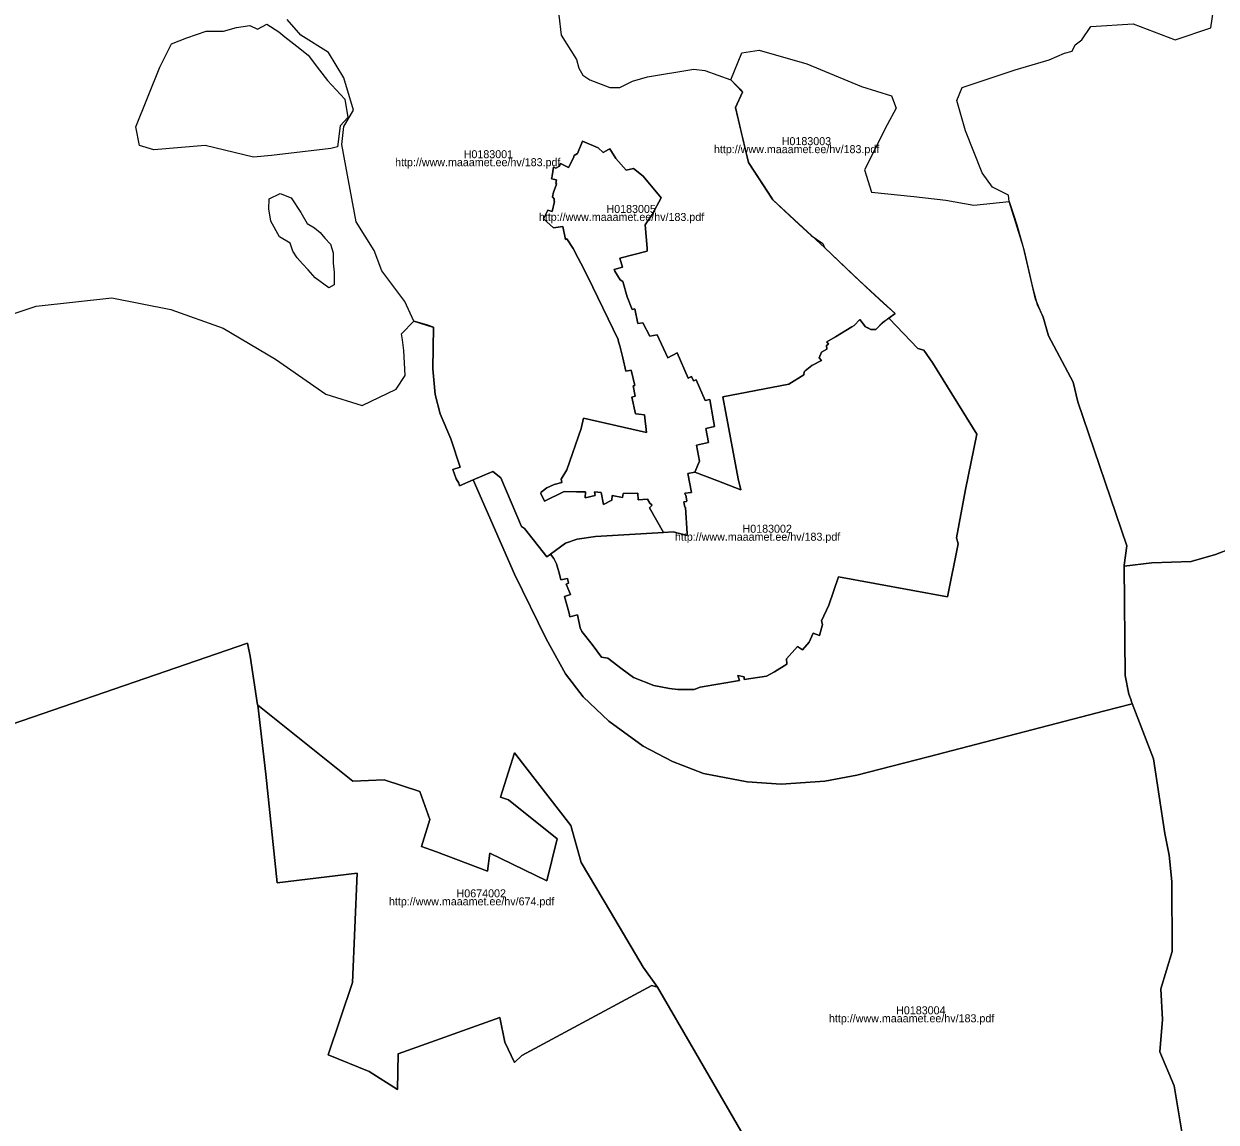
# Model space of a CAD drawing. Extents: x 369010 to 739155, y 6377141 to 6634081.
# Drawn here: x 471593 to 475318, y 6531445 to 6534877 of the extents above; entities that cross this region are included whole.
import ezdxf

# ---------------------------------------------------------------- set-up
doc = ezdxf.new("R2010")
doc.units = 0
for name, color, linetype in [('H_LINK', 7, 'Continuous'), ('H_PIIR', 7, 'Continuous'), ('H_TUNNUS', 7, 'Continuous')]:
    doc.layers.add(name, color=color, linetype=linetype)

msp = doc.modelspace()

# ---------------------------------------------------------------- linework, layer by layer
at = {"layer": 'H_PIIR'}
for points in [[(475364.8401, 6533237.45), (475316.2799, 6533219.06), (475239.38, 6533197), (475117.2199, 6533193.4201), (475030.3393, 6533182.4787), (475030.3, 6533186.16), (475039.08, 6533246.02), (474885.8701, 6533696.14), (474870.9001, 6533757.78), (474794.1099, 6533901.8299), (474777.21, 6533960.43), (474753.57, 6534017.02), (474715.6, 6534178.31), (474671.2069, 6534322.0591), (474668.6933, 6534341.3737), (474619.0839, 6534366.5091), (474587.3338, 6534411.4884), (474534.313, 6534542.6387), (474507.3254, 6534637.8889), (474524.788, 6534677.5765), (474689.8883, 6534733.1391), (474796.251, 6534764.8892), (474843.8761, 6534785.5267), (474867.6886, 6534791.8767), (474877.2137, 6534810.9267), (474898.1158, 6534826.8018), (474925.8971, 6534869.1352), (475058.189, 6534877.0727), (475189.9518, 6534826.8018), (475300.8124, 6534864.3727), (475319.3333, 6534984.7583)], [(473264.6791, 6534903.9142), (473271.84, 6534841.7599), (473319.9099, 6534765.46), (473326.52, 6534738.5501), (473339.75, 6534716.0601), (473361.3599, 6534701.4999), (473423.61, 6534678.29), (473454.49, 6534678.29), (473494.1801, 6534698.1301), (473541.3699, 6534711.81), (473686.46, 6534735.6301), (473719.98, 6534731.6601), (473801.71, 6534701.78), (473831.2103, 6534672.9801), (473838.55, 6534663.64), (473815.9, 6534615.14), (473835.0722, 6534534.3921), (473856.5102, 6534444.1018), (473918.52, 6534350.37), (473932.8083, 6534327.2742), (473969.4036, 6534293.0652), (474015.2445, 6534250.2137), (474052.5765, 6534215.3161), (474088.572, 6534191.1336), (474093.8573, 6534178.106), (474222.6456, 6534056.3373), (474280.0158, 6534002.7083), (474314.98, 6533971.86), (474294.8903, 6533957.742), (474271.0477, 6533938.6733), (474255, 6533922.0099), (474238.68, 6533922.46), (474229.6719, 6533926.8398), (474222.3701, 6533930.39), (474204.6842, 6533953.5152), (474187.2001, 6533934.2001), (474179.9671, 6533929.9246), (474128.41, 6533899.4499), (474101.2601, 6533883.81), (474106.8199, 6533876.4299), (474100.17, 6533871.8801), (474101.0799, 6533860.9601), (474084.61, 6533851.5599), (474077.93, 6533833.6799), (474084.61, 6533825.33), (474054.3599, 6533809.0501), (474033.38, 6533792.7399), (474030.36, 6533789.49), (474030.01, 6533780.7201), (473982.64, 6533750.6399), (473776.47, 6533712.0401), (473825.06, 6533455.58), (473832.47, 6533420.97), (473758.02, 6533450.6701), (473689.2901, 6533475.82), (473704.2301, 6533510.8), (473693.94, 6533560.2699), (473732.13, 6533568.4801), (473723.97, 6533612.35), (473750.8299, 6533618.81), (473747.82, 6533636.9299), (473735.9299, 6533703.25), (473721.87, 6533700.4399), (473693.1599, 6533764.6601), (473685.03, 6533761.1401), (473678.2601, 6533774.69), (473668.28, 6533770.2599), (473634.4201, 6533848.57), (473604.3699, 6533833.6), (473571.3799, 6533905.2899), (473548.8999, 6533901.5), (473527.23, 6533943.23), (473511.04, 6533940.18), (473501.99, 6533986.0699), (473493.16, 6533984.62), (473478.28, 6534024.0999), (473464.32, 6534071.77), (473455.5601, 6534076.6599), (473439.3701, 6534104.09), (473437.5499, 6534109.72), (473463.1301, 6534117.1601), (473455.16, 6534144.98), (473540.66, 6534166.83), (473540.1, 6534175.9901), (473533.78, 6534248.94), (473555.67, 6534281.27), (473584.2201, 6534333.7), (473528.2901, 6534400.54), (473497.5699, 6534425.36), (473474.7, 6534419.9099), (473442.07, 6534455.8401), (473423.2601, 6534486.2799), (473419.33, 6534484.42), (473402.78, 6534474.68), (473386.9001, 6534489.8401), (473338.53, 6534510.77), (473322.99, 6534471.8399), (473312.16, 6534465.23), (473309.9, 6534458.23), (473294.31, 6534428.35), (473275.84, 6534437.2399), (473276.0399, 6534437.7899), (473269.59, 6534440.1299), (473266.09, 6534431.79), (473255, 6534426.14), (473247.45, 6534428.92), (473243, 6534401.5401), (473243.6899, 6534401.4), (473241.85, 6534392.2099), (473257.0099, 6534389.2), (473254.54, 6534378.31), (473256.77, 6534378.03), (473256.12, 6534373.02), (473247.6, 6534350.5), (473244.3099, 6534336.69), (473249.41, 6534329.85), (473249.41, 6534322.2), (473251.13, 6534321.8099), (473243, 6534291.1), (473229.9501, 6534294.2701), (473216.77, 6534267.5999), (473247.8701, 6534239.75), (473276.7501, 6534243.77), (473285.4301, 6534203.1501), (473289.3701, 6534205.2599), (473308.71, 6534174.8701), (473324.81, 6534144.44), (473341.8801, 6534114.07), (473370.48, 6534053.89), (473449.55, 6533891.1), (473450.8299, 6533882.98), (473454.71, 6533870.8201), (473463.92, 6533833.1399), (473473.56, 6533791.5799), (473489.79, 6533795), (473502.09, 6533747.1399), (473496.5501, 6533745.83), (473503.08, 6533713.2001), (473492.4399, 6533710.72), (473503.72, 6533658.4401), (473513.94, 6533657.37), (473532.1, 6533654.8299), (473538.19, 6533600.42), (473341.3301, 6533645.0899), (473333.9, 6533612.8501), (473288.8101, 6533483.5601), (473271.19, 6533454.54), (473273.7199, 6533444.2999), (473249.38, 6533437.59), (473226.4199, 6533427.0901), (473209.2001, 6533413.6499), (473207.8799, 6533410.05), (473219.39, 6533385.3799), (473281.03, 6533416.1301), (473319.74, 6533415.27), (473347.85, 6533414.8299), (473346.5801, 6533396.4601), (473378.1399, 6533403.79), (473376.08, 6533414.73), (473396.48, 6533412.6901), (473403.75, 6533374.68), (473430.36, 6533389.0501), (473431.3901, 6533403.2799), (473463.5699, 6533396.74), (473465.2799, 6533409.2201), (473510.8299, 6533410.9201), (473511.9599, 6533390.0299), (473541.26, 6533391.3401), (473548.54, 6533378.89), (473555.3199, 6533374.5701), (473554.0899, 6533370.87), (473547.3001, 6533364.7001), (473590.94, 6533287.7), (473379.09, 6533275.39), (473321.6901, 6533266.7201), (473285.3101, 6533254.8), (473238.21, 6533220.03), (473226.4199, 6533211.44), (473157.38, 6533300.1901), (473147.17, 6533306.4401), (473082.8901, 6533458.91), (473058.33, 6533478.3901), (472996.63, 6533452.4501), (472954.35, 6533433.9801), (472951.7199, 6533441.4401), (472943.3, 6533455.2199), (472933.3299, 6533484.92), (472955.56, 6533492.2801), (472926.68, 6533580.31), (472893.93, 6533658.3299), (472877.55, 6533718.82), (472870.17, 6533799.52), (472872.819, 6533929.3015), (472851.7959, 6533936.8073), (472811.4469, 6533948.0521), (472783.6656, 6534009.5679), (472711.5665, 6534104.8181), (472687.754, 6534168.3182), (472631.5299, 6534258.2767), (472598.3246, 6534432.4258), (472586.4183, 6534499.8947), (472592.3715, 6534556.1188), (472622.7986, 6534607.0511), (472592.3715, 6534708.2545), (472544.7464, 6534786.9682), (472458.7566, 6534841.2079), (472415.1576, 6534890.5327)], [(471456.7687, 6533936.3928), (471631.3941, 6533994.6012), (471868.1966, 6534021.0596), (472052.0824, 6533984.0179), (472216.1244, 6533925.8094), (472378.8435, 6533829.2363), (472536.2709, 6533719.434), (472650.0419, 6533684.2885), (472755.8755, 6533735.0886), (472784.4505, 6533777.9512), (472779.9614, 6533856.1092), (472775.7281, 6533889.4468), (472773.0822, 6533908.3645), (472811.4469, 6533948.0521), (472870.83, 6533929.4), (472872.819, 6533929.3015), (472870.17, 6533799.52), (472877.55, 6533718.82), (472893.93, 6533658.3299), (472926.68, 6533580.31), (472955.56, 6533492.2801), (472933.3299, 6533484.92), (472943.3, 6533455.2199), (472951.7199, 6533441.4401), (472954.35, 6533433.9801), (472996.63, 6533452.4501), (473125.5301, 6533157.43), (473225.17, 6532955.5399), (473284.7299, 6532845.77), (473340.1701, 6532774.3), (473420.4101, 6532698.7599), (473527.33, 6532620.58), (473619.01, 6532571.72), (473716.56, 6532535.0001), (473852.22, 6532508.9399), (473958.4, 6532500.9199), (474095.4601, 6532510.95), (474195.1699, 6532529.03), (474418.35, 6532586.53), (474969.68, 6532730.25), (475051.0512, 6532751.8103), (475055.993, 6532753.1197), (475122.11, 6532580.6201), (475157.79, 6532346.77), (475170.7, 6532279.62), (475179.92, 6532197.13), (475180.1401, 6531978.1199), (475145.27, 6531862.49), (475150.0199, 6531765.75), (475141.82, 6531664.68), (475187.2, 6531559.17), (475224.34, 6531333.9)], [(475224.34, 6531333.9), (475187.2, 6531559.17), (475141.82, 6531664.68), (475150.0199, 6531765.75), (475145.27, 6531862.49), (475180.1401, 6531978.1199), (475179.92, 6532197.13), (475170.7, 6532279.62), (475157.79, 6532346.77), (475122.11, 6532580.6201), (475055.993, 6532753.1197), (475052.6201, 6532761.92), (475052.6201, 6532763.82), (475045.32, 6532782.9999), (475033.98, 6532841.3399), (475030.3393, 6533182.4787), (475117.2199, 6533193.4201), (475239.38, 6533197), (475316.2799, 6533219.06), (475364.8401, 6533237.45)], [(471298.02, 6532600.1899), (472291.7299, 6532941.6499), (472299.9101, 6532901.4001), (472322.54, 6532749.22), (472323.4308, 6532748.5051), (472348.6, 6532532.34), (472384.32, 6532192.71), (472633.76, 6532223.5301), (472619.4199, 6531881.57), (472544.08, 6531655.47), (472672.0301, 6531603.38), (472760.68, 6531547.1299), (472762.84, 6531658.78), (473079.9801, 6531772.09), (473095.5101, 6531695.4399), (473125.79, 6531631.68), (473149.0499, 6531653.74), (473554.59, 6531872.36), (473572.46, 6531867.61), (473692.5499, 6531661.3499), (473886.5099, 6531326.8101)], [(473886.5099, 6531326.8101), (473692.5499, 6531661.3499), (473572.46, 6531867.61), (473527.51, 6531929.8601), (473425.65, 6532102.7899), (473334.17, 6532256.8499), (473302.1001, 6532372.56), (473126.0599, 6532599.5599), (473082.36, 6532461.2201), (473107.5099, 6532452.4199), (473259.04, 6532330.42), (473226.9699, 6532199.63), (473048.41, 6532285.7801), (473041.1799, 6532229.8101), (472882.1101, 6532289.55), (472835.59, 6532306.5301), (472861.36, 6532391.4201), (472829.93, 6532478.83), (472718.33, 6532515.2999), (472620.24, 6532510.2701), (472323.4308, 6532748.5051), (472322.54, 6532749.22), (472299.9101, 6532901.4001), (472291.7299, 6532941.6499), (471298.02, 6532600.1899)]]:
    msp.add_lwpolyline(points, dxfattribs=at)
for points in [[(472352.4722, 6534875.8217), (472389.5923, 6534851.568), (472408.4238, 6534836.6243), (472446.1025, 6534806.7245), (472481.06, 6534778.984), (472516.7788, 6534732.1527), (472541.3851, 6534699.6089), (472595.3602, 6534641.665), (472605.0715, 6534584.5615), (472581.2589, 6534558.3677), (472573.3214, 6534492.4863), (472551.8901, 6534486.9301), (472366.946, 6534465.4988), (472310.5897, 6534459.9425), (472158.9831, 6534496.4551), (471998.6453, 6534483.7551), (471954.1952, 6534496.4551), (471943.0827, 6534555.1927), (472017.6953, 6534741.7243), (472054.2079, 6534814.7495), (472101.833, 6534833.0058), (472162.1581, 6534854.4371), (472216.1332, 6534854.4371), (472257.4083, 6534865.5496), (472298.6834, 6534871.8996), (472323.1034, 6534860.7405)], [(474294.8903, 6533957.742), (474314.98, 6533971.86), (474189.169, 6534087.9893), (474093.8573, 6534178.106), (473932.8083, 6534327.2742), (473856.5102, 6534444.1018), (473815.9, 6534615.14), (473838.55, 6534663.64), (473801.71, 6534701.78), (473836.4448, 6534786.4037), (473890.4199, 6534794.8704), (474038.5869, 6534751.4787), (474210.0372, 6534681.6285), (474303.1707, 6534651.9951), (474317.9874, 6534613.8951), (474290.4707, 6534560.9783), (474219.5622, 6534421.278), (474240.7289, 6534351.4279), (474373.55, 6534337.1403), (474473.5627, 6534326.0278), (474560.8754, 6534310.1528), (474671.2069, 6534322.0591), (474686.1, 6534278.36), (474695.0392, 6534248.643), (474718.142, 6534167.5119), (474744.5884, 6534053.7612), (474759.0763, 6533999.8363), (474777.21, 6533960.43), (474794.1099, 6533901.8299), (474870.9001, 6533757.78), (474885.8701, 6533696.14), (475039.08, 6533246.02), (475030.3, 6533186.16), (475030.3393, 6533182.4787), (475033.98, 6532841.3399), (475045.32, 6532782.9999), (475052.6201, 6532763.82), (475052.6201, 6532761.92), (475055.993, 6532753.1197), (475051.05, 6532751.81), (474969.68, 6532730.25), (474418.35, 6532586.53), (474195.1699, 6532529.03), (474095.4601, 6532510.95), (473958.4, 6532500.9199), (473852.22, 6532508.9399), (473716.56, 6532535.0001), (473619.01, 6532571.72), (473527.33, 6532620.58), (473420.4101, 6532698.7599), (473340.1701, 6532774.3), (473284.7299, 6532845.77), (473225.17, 6532955.5399), (473125.5301, 6533157.43), (472996.63, 6533452.4501), (473058.33, 6533478.3901), (473082.8901, 6533458.91), (473147.17, 6533306.4401), (473157.38, 6533300.1901), (473226.4199, 6533211.44), (473238.21, 6533220.03), (473248.4701, 6533206.0301), (473256.9399, 6533189.8499), (473266.4, 6533157.27), (473270.9401, 6533139.95), (473291.32, 6533144.42), (473294.76, 6533129.12), (473287.33, 6533126.16), (473300.2499, 6533094.25), (473282.3799, 6533088.16), (473296.06, 6533035.42), (473299.1199, 6533024.7399), (473322.7599, 6533030.0801), (473331.0001, 6532990.03), (473336.34, 6532978.5899), (473368.3699, 6532938.15), (473398.11, 6532898.4799), (473417.18, 6532894.66), (473462.17, 6532861.0901), (473498.02, 6532834.3899), (473561.32, 6532809.21), (473609.78, 6532800.3099), (473636.47, 6532797.25), (473686.8099, 6532797.25), (473705.8699, 6532804.88), (473828.3101, 6532825.5), (473823.7301, 6532840.7599), (473842.8, 6532836.94), (473842.8, 6532828.55), (473912.9599, 6532839.23), (473938.13, 6532852.2), (473976.26, 6532875.86), (473975.3399, 6532893.15), (474010.42, 6532931.2999), (474025.6801, 6532920.62), (474046.2699, 6532945.04), (474058.4701, 6532973.27), (474078.3, 6532966.4), (474088.21, 6532999.9699), (474085.16, 6533011.41), (474108.0399, 6533061.01), (474137.74, 6533149.18), (474478.28, 6533086.7101), (474511.9699, 6533252.1901), (474507, 6533271.2501), (474534.91, 6533422.4601), (474570.52, 6533594.79), (474432.3099, 6533816.5001), (474404.85, 6533857.3799), (474386.3101, 6533863.05), (474295.91, 6533956.53)], [(473247.8701, 6534239.75), (473216.77, 6534267.5999), (473229.9501, 6534294.2701), (473243, 6534291.1), (473251.13, 6534321.8099), (473249.41, 6534322.2), (473249.41, 6534329.85), (473244.3099, 6534336.69), (473247.6, 6534350.5), (473256.12, 6534373.02), (473256.77, 6534378.03), (473254.54, 6534378.31), (473257.0099, 6534389.2), (473241.85, 6534392.2099), (473243.6899, 6534401.4), (473243, 6534401.5401), (473247.45, 6534428.92), (473255, 6534426.14), (473266.09, 6534431.79), (473269.59, 6534440.1299), (473276.0399, 6534437.7899), (473275.84, 6534437.2399), (473294.31, 6534428.35), (473309.9, 6534458.23), (473312.16, 6534465.23), (473322.99, 6534471.8399), (473338.53, 6534510.77), (473386.9001, 6534489.8401), (473402.78, 6534474.68), (473419.33, 6534484.42), (473423.2601, 6534486.2799), (473442.07, 6534455.8401), (473474.7, 6534419.9099), (473497.5699, 6534425.36), (473528.2901, 6534400.54), (473584.2201, 6534333.7), (473555.67, 6534281.27), (473533.78, 6534248.94), (473540.1, 6534175.9901), (473540.66, 6534166.83), (473455.16, 6534144.98), (473463.1301, 6534117.1601), (473437.5499, 6534109.72), (473439.3701, 6534104.09), (473455.5601, 6534076.6599), (473464.32, 6534071.77), (473478.28, 6534024.0999), (473493.16, 6533984.62), (473501.99, 6533986.0699), (473511.04, 6533940.18), (473527.23, 6533943.23), (473548.8999, 6533901.5), (473571.3799, 6533905.2899), (473604.3699, 6533833.6), (473634.4201, 6533848.57), (473668.28, 6533770.2599), (473678.2601, 6533774.69), (473685.03, 6533761.1401), (473693.1599, 6533764.6601), (473721.87, 6533700.4399), (473735.9299, 6533703.25), (473747.82, 6533636.9299), (473750.8299, 6533618.81), (473723.97, 6533612.35), (473732.13, 6533568.4801), (473693.94, 6533560.2699), (473704.2301, 6533510.8), (473689.2901, 6533475.82), (473667.7799, 6533471.81), (473679.02, 6533412.76), (473658.1101, 6533410.41), (473658.83, 6533406.08), (473661.18, 6533404.3899), (473664.4901, 6533386.4), (473663.64, 6533384.9601), (473654.6901, 6533383.2501), (473656.09, 6533377.52), (473657.86, 6533366.78), (473659.8401, 6533366), (473664.8799, 6533284.9599), (473665.31, 6533278.35), (473621.5699, 6533289.6799), (473590.94, 6533287.7), (473547.3001, 6533364.7001), (473554.0899, 6533370.87), (473555.3199, 6533374.5701), (473548.54, 6533378.89), (473541.26, 6533391.3401), (473511.9599, 6533390.0299), (473510.8299, 6533410.9201), (473465.2799, 6533409.2201), (473463.5699, 6533396.74), (473431.3901, 6533403.2799), (473430.36, 6533389.0501), (473403.75, 6533374.68), (473396.48, 6533412.6901), (473376.08, 6533414.73), (473378.1399, 6533403.79), (473346.5801, 6533396.4601), (473347.85, 6533414.8299), (473319.74, 6533415.27), (473281.03, 6533416.1301), (473219.39, 6533385.3799), (473207.8799, 6533410.05), (473209.2001, 6533413.6499), (473226.4199, 6533427.0901), (473249.38, 6533437.59), (473273.7199, 6533444.2999), (473271.19, 6533454.54), (473288.8101, 6533483.5601), (473333.9, 6533612.8501), (473341.3301, 6533645.0899), (473538.19, 6533600.42), (473532.1, 6533654.8299), (473513.94, 6533657.37), (473503.72, 6533658.4401), (473492.4399, 6533710.72), (473503.08, 6533713.2001), (473496.5501, 6533745.83), (473502.09, 6533747.1399), (473489.79, 6533795), (473473.56, 6533791.5799), (473463.92, 6533833.1399), (473454.71, 6533870.8201), (473450.8299, 6533882.98), (473449.55, 6533891.1), (473370.48, 6534053.89), (473341.8801, 6534114.07), (473324.81, 6534144.44), (473308.71, 6534174.8701), (473289.3701, 6534205.2599), (473285.4301, 6534203.1501), (473276.7501, 6534243.77)], [(472391.42, 6534211.3131), (472364.9616, 6534260.2611), (472358.347, 6534298.6257), (472359.0085, 6534330.3758), (472393.4044, 6534346.9123), (472428.4618, 6534333.6831), (472458.2274, 6534287.3809), (472478.0712, 6534252.985), (472500.5609, 6534239.7558), (472518.4203, 6534225.2037), (472532.9724, 6534207.3443), (472550.8318, 6534188.162), (472559.4308, 6534161.0421), (472559.4308, 6534129.2921), (472562.0766, 6534100.8493), (472562.7381, 6534076.3753), (472562.7381, 6534061.8232), (472546.2016, 6534052.5627), (472503.2067, 6534082.9899), (472480.7171, 6534108.7868), (472463.5191, 6534126.6462), (472446.9826, 6534145.8286), (472433.092, 6534166.3338), (472424.493, 6534192.1307)], [(474294.8903, 6533957.742), (474295.91, 6533956.53), (474386.3101, 6533863.05), (474404.85, 6533857.3799), (474432.3099, 6533816.5001), (474570.52, 6533594.79), (474534.91, 6533422.4601), (474507, 6533271.2501), (474511.9699, 6533252.1901), (474478.28, 6533086.7101), (474137.74, 6533149.18), (474108.0399, 6533061.01), (474085.16, 6533011.41), (474088.21, 6532999.9699), (474078.3, 6532966.4), (474058.4701, 6532973.27), (474046.2699, 6532945.04), (474025.6801, 6532920.62), (474010.42, 6532931.2999), (473975.3399, 6532893.15), (473976.26, 6532875.86), (473938.13, 6532852.2), (473912.9599, 6532839.23), (473842.8, 6532828.55), (473842.8, 6532836.94), (473823.7301, 6532840.7599), (473828.3101, 6532825.5), (473705.8699, 6532804.88), (473686.8099, 6532797.25), (473636.47, 6532797.25), (473609.78, 6532800.3099), (473561.32, 6532809.21), (473498.02, 6532834.3899), (473462.17, 6532861.0901), (473417.18, 6532894.66), (473398.11, 6532898.4799), (473368.3699, 6532938.15), (473336.34, 6532978.5899), (473331.0001, 6532990.03), (473322.7599, 6533030.0801), (473299.1199, 6533024.7399), (473296.06, 6533035.42), (473282.3799, 6533088.16), (473300.2499, 6533094.25), (473287.33, 6533126.16), (473294.76, 6533129.12), (473291.32, 6533144.42), (473270.9401, 6533139.95), (473266.4, 6533157.27), (473256.9399, 6533189.8499), (473248.4701, 6533206.0301), (473238.21, 6533220.03), (473285.3101, 6533254.8), (473321.6901, 6533266.7201), (473379.09, 6533275.39), (473590.94, 6533287.7), (473621.5699, 6533289.6799), (473665.31, 6533278.35), (473664.8799, 6533284.9599), (473659.8401, 6533366), (473657.86, 6533366.78), (473656.09, 6533377.52), (473654.6901, 6533383.2501), (473663.64, 6533384.9601), (473664.4901, 6533386.4), (473661.18, 6533404.3899), (473658.83, 6533406.08), (473658.1101, 6533410.41), (473679.02, 6533412.76), (473667.7799, 6533471.81), (473689.2901, 6533475.82), (473758.02, 6533450.6701), (473832.47, 6533420.97), (473825.06, 6533455.58), (473776.47, 6533712.0401), (473982.64, 6533750.6399), (474030.01, 6533780.7201), (474030.36, 6533789.49), (474033.38, 6533792.7399), (474054.3599, 6533809.0501), (474084.61, 6533825.33), (474077.93, 6533833.6799), (474084.61, 6533851.5599), (474101.0799, 6533860.9601), (474100.17, 6533871.8801), (474106.8199, 6533876.4299), (474101.2601, 6533883.81), (474128.41, 6533899.4499), (474179.9671, 6533929.9246), (474187.2001, 6533934.2001), (474204.6842, 6533953.5152), (474222.3701, 6533930.39), (474238.68, 6533922.46), (474255, 6533922.0099), (474277.94, 6533945.8301)], [(472323.4308, 6532748.5051), (472620.24, 6532510.2701), (472718.33, 6532515.2999), (472829.93, 6532478.83), (472861.36, 6532391.4201), (472835.59, 6532306.5301), (472882.1101, 6532289.55), (473041.1799, 6532229.8101), (473048.41, 6532285.7801), (473226.9699, 6532199.63), (473259.04, 6532330.42), (473107.5099, 6532452.4199), (473082.36, 6532461.2201), (473126.0599, 6532599.5599), (473302.1001, 6532372.56), (473334.17, 6532256.8499), (473425.65, 6532102.7899), (473527.51, 6531929.8601), (473572.46, 6531867.61), (473554.59, 6531872.36), (473149.0499, 6531653.74), (473125.79, 6531631.68), (473095.5101, 6531695.4399), (473079.9801, 6531772.09), (472762.84, 6531658.78), (472760.68, 6531547.1299), (472672.0301, 6531603.38), (472544.08, 6531655.47), (472619.4199, 6531881.57), (472633.76, 6532223.5301), (472384.32, 6532192.71), (472348.6, 6532532.34)]]:
    msp.add_lwpolyline(points, close=True, dxfattribs=at)

# ---------------------------------------------------------------- texts
at = {"layer": 'H_LINK'}
for s, rotation, p in [('http://www.maaamet.ee/hv/183.pdf', 360, (473748.8365, 6534472.8712)), ('http://www.maaamet.ee/hv/183.pdf', 0, (472752.7343, 6534432.1372)), ('http://www.maaamet.ee/hv/183.pdf', 360, (473201.8799, 6534261.0912)), ('http://www.maaamet.ee/hv/674.pdf', 0, (472733.5249, 6532122.8175)), ('http://www.maaamet.ee/hv/183.pdf', 0, (474108.1715, 6531757.3698))]:
    msp.add_text(s, height=25, rotation=rotation, dxfattribs=at).set_placement(p)
msp.add_text('http://www.maaamet.ee/hv/183.pdf', height=25, dxfattribs=at).set_placement((473626.89, 6533261.9533))
at = {"layer": 'H_TUNNUS'}
for s, rotation, p in [('H0183003', 360, (473960.6911, 6534497.8712)), ('H0183001', 0, (472967.0882, 6534457.1372)), ('H0183005', 360, (473413.1089, 6534286.0912)), ('H0674002', 0, (472944.7538, 6532147.8175)), ('H0183004', 0, (474318.1507, 6531782.3698))]:
    msp.add_text(s, height=25, rotation=rotation, dxfattribs=at).set_placement(p)
msp.add_text('H0183002', height=25, dxfattribs=at).set_placement((473838.119, 6533286.9533))

doc.saveas('drawing.dxf')
